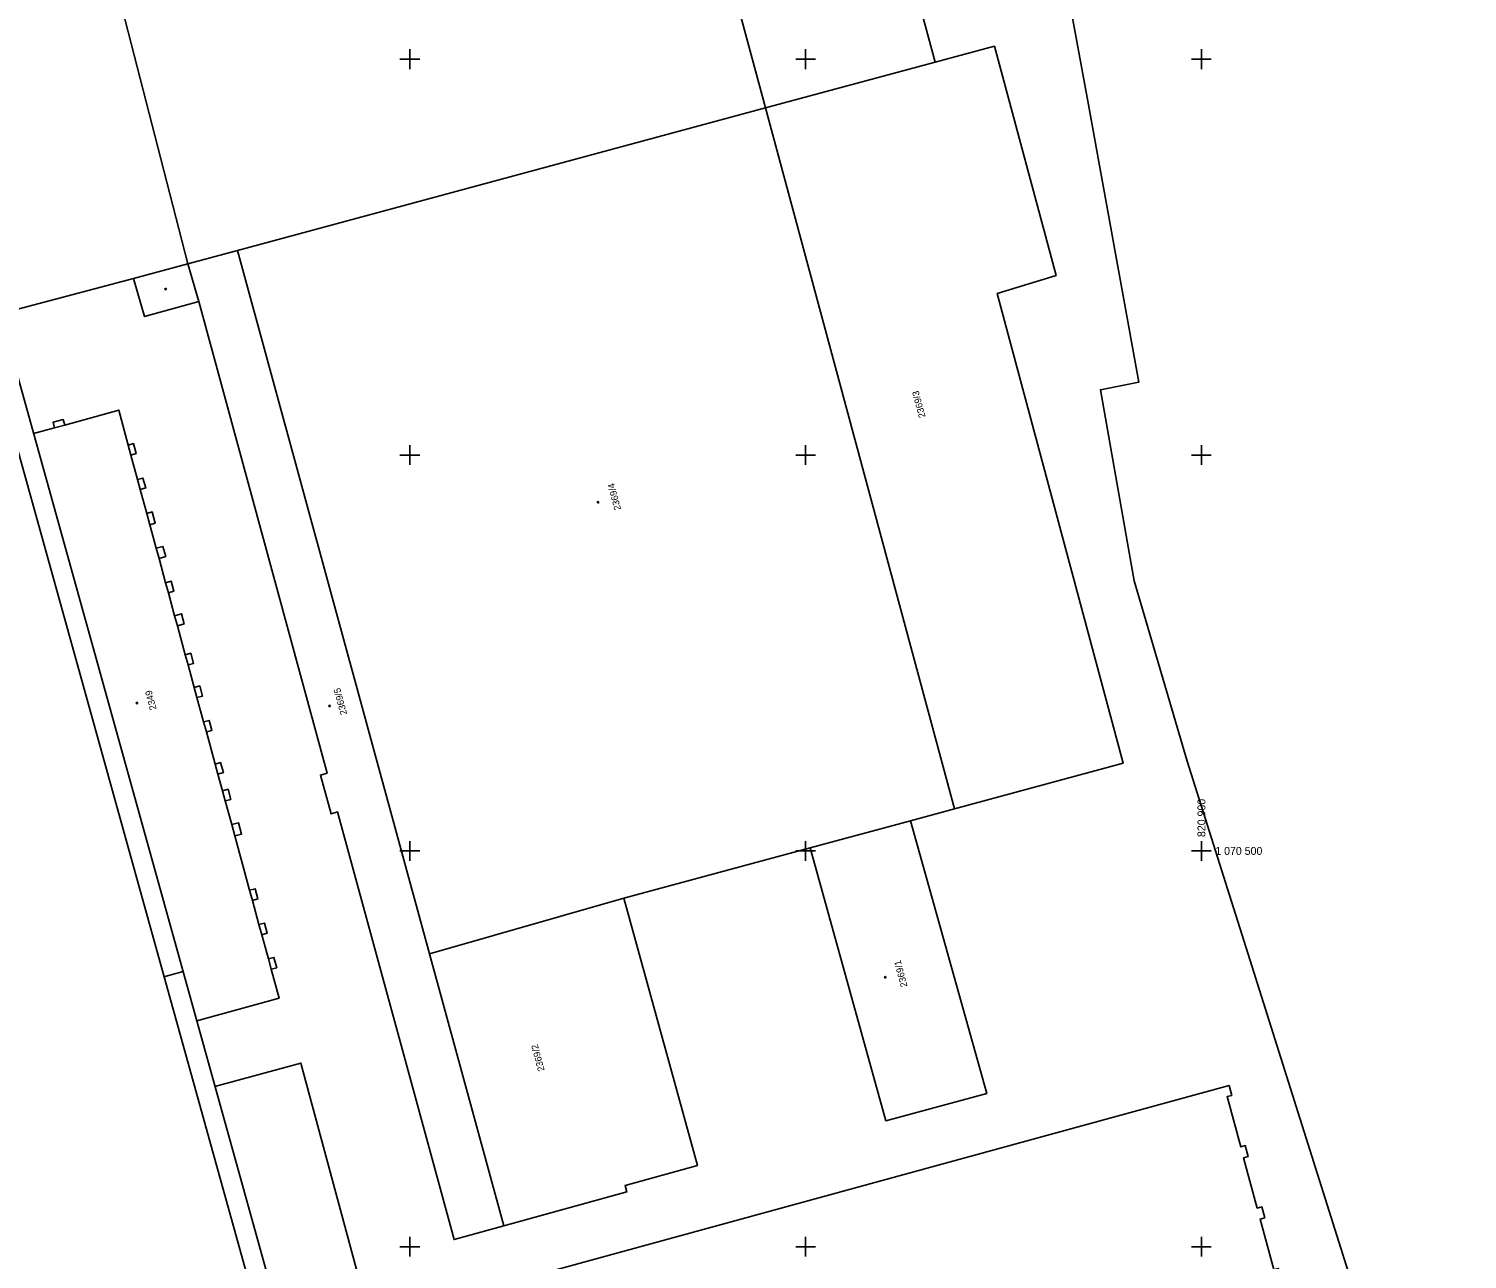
# Model space of a CAD drawing. Extents: x -821172 to -820632, y -1070921 to -1069931.
# Drawn here: x -821048.1 to -820866.4, y -1070551.6 to -1070396.2 of the extents above; entities that cross this region are included whole.
import ezdxf

# ---------------------------------------------------------------- set-up
doc = ezdxf.new("R2010")
doc.units = 0
for name, color, linetype in [('Ram', 7, 'Continuous'), ('Sit', 7, 'Continuous'), ('Vrstva 53', 7, 'Continuous'), ('Vrstva 55', 7, 'Continuous'), ('Vrstva 56', 7, 'Continuous'), ('Vrstva 57', 7, 'Continuous'), ('Vrstva 59', 7, 'Continuous')]:
    doc.layers.add(name, color=color, linetype=linetype)

msp = doc.modelspace()

# ---------------------------------------------------------------- linework, layer by layer
at = {"layer": 'Ram'}
msp.add_line((-821028.65, -1070515.23), (-821031.06, -1070515.9), dxfattribs=at)
for points in [[(-820775.54, -1070880.81), (-820918.62, -1070920.57), (-821143.51, -1070111.23)], [(-820916.88, -1070917.49), (-821140.43, -1070112.97)]]:
    msp.add_lwpolyline(points, dxfattribs=at)
at = {"layer": 'Sit'}
for p, q in [((-821000, -1070398.75), (-821000, -1070400)), ((-820950, -1070398.75), (-820950, -1070400)), ((-820900, -1070398.75), (-820900, -1070400)), ((-821001.25, -1070400), (-821000, -1070400)), ((-820998.75, -1070400), (-821000, -1070400)), ((-821000, -1070401.25), (-821000, -1070400)), ((-820951.25, -1070400), (-820950, -1070400)), ((-820948.75, -1070400), (-820950, -1070400)), ((-820950, -1070401.25), (-820950, -1070400)), ((-820901.25, -1070400), (-820900, -1070400)), ((-820898.75, -1070400), (-820900, -1070400)), ((-820900, -1070401.25), (-820900, -1070400)), ((-821001.25, -1070450), (-821000, -1070450)), ((-821000, -1070448.75), (-821000, -1070450)), ((-820998.75, -1070450), (-821000, -1070450)), ((-821000, -1070451.25), (-821000, -1070450)), ((-820951.25, -1070450), (-820950, -1070450)), ((-820950, -1070448.75), (-820950, -1070450)), ((-820948.75, -1070450), (-820950, -1070450)), ((-820950, -1070451.25), (-820950, -1070450)), ((-820901.25, -1070450), (-820900, -1070450)), ((-820900, -1070448.75), (-820900, -1070450)), ((-820898.75, -1070450), (-820900, -1070450)), ((-820900, -1070451.25), (-820900, -1070450)), ((-821000, -1070498.75), (-821000, -1070500)), ((-820950, -1070498.75), (-820950, -1070500)), ((-820900, -1070498.75), (-820900, -1070500)), ((-821001.25, -1070500), (-821000, -1070500)), ((-820998.75, -1070500), (-821000, -1070500)), ((-821000, -1070501.25), (-821000, -1070500)), ((-820951.25, -1070500), (-820950, -1070500)), ((-820948.75, -1070500), (-820950, -1070500)), ((-820950, -1070501.25), (-820950, -1070500)), ((-820901.25, -1070500), (-820900, -1070500)), ((-820898.75, -1070500), (-820900, -1070500)), ((-820900, -1070501.25), (-820900, -1070500)), ((-821001.25, -1070550), (-821000, -1070550)), ((-821000, -1070548.75), (-821000, -1070550)), ((-820998.75, -1070550), (-821000, -1070550)), ((-821000, -1070551.25), (-821000, -1070550)), ((-820951.25, -1070550), (-820950, -1070550)), ((-820950, -1070548.75), (-820950, -1070550)), ((-820948.75, -1070550), (-820950, -1070550)), ((-820950, -1070551.25), (-820950, -1070550)), ((-820901.25, -1070550), (-820900, -1070550)), ((-820900, -1070548.75), (-820900, -1070550)), ((-820898.75, -1070550), (-820900, -1070550)), ((-820900, -1070551.25), (-820900, -1070550))]:
    msp.add_line(p, q, dxfattribs=at)
at = {"layer": 'Vrstva 53'}
msp.add_lwpolyline([(-820793.34, -1070807.43), (-820797.89, -1070798.01), (-820802.49, -1070786.9), (-820807.86, -1070771.6), (-820839.34, -1070671.73), (-820847.49, -1070649.05), (-820862.12, -1070611.55), (-820870.18, -1070588.9), (-820893.88, -1070513.71), (-820901.78, -1070488.65), (-820908.48, -1070465.88), (-820912.77, -1070441.75), (-820907.91, -1070440.8), (-820914.43, -1070404.83), (-820920.34, -1070372.85), (-820926.76, -1070341.17), (-820933.59, -1070313.73), (-820939.94, -1070294.5), (-820946.33, -1070279.59), (-820953.63, -1070265.09), (-820959.73, -1070254.91)], dxfattribs=at)
at = {"layer": 'Vrstva 55'}
for p, q in [((-820957.29, -1070313.09), (-820933.62, -1070400.37)), ((-820978.59, -1070318.91), (-820955.07, -1070406.16)), ((-821050.57, -1070338.41), (-821028.04, -1070425.85)), ((-820933.62, -1070400.37), (-820955.07, -1070406.16)), ((-820955.07, -1070406.16), (-821021.76, -1070424.16)), ((-820955.07, -1070406.16), (-820931.21, -1070494.68)), ((-821021.76, -1070424.16), (-821028.04, -1070425.85)), ((-821021.76, -1070424.16), (-820997.52, -1070512.98)), ((-821028.04, -1070425.85), (-821026.67, -1070430.62)), ((-820931.21, -1070494.68), (-820936.77, -1070496.18)), ((-820936.77, -1070496.18), (-820949.42, -1070499.6)), ((-820949.42, -1070499.6), (-820972.96, -1070505.96)), ((-820972.96, -1070505.96), (-820997.52, -1070512.98)), ((-820997.52, -1070512.98), (-820988.14, -1070547.37))]:
    msp.add_line(p, q, dxfattribs=at)
for points in [[(-820793.34, -1070807.43), (-820797.89, -1070798.01), (-820802.49, -1070786.9), (-820807.86, -1070771.6), (-820839.34, -1070671.73), (-820847.49, -1070649.05), (-820862.12, -1070611.55), (-820870.18, -1070588.9), (-820893.88, -1070513.71), (-820901.78, -1070488.65), (-820908.48, -1070465.88), (-820912.77, -1070441.75), (-820907.91, -1070440.8), (-820914.43, -1070404.83), (-820920.34, -1070372.85), (-820926.76, -1070341.17), (-820933.59, -1070313.73), (-820939.94, -1070294.5), (-820946.33, -1070279.59), (-820953.63, -1070265.09), (-820959.73, -1070254.91)], [(-820933.62, -1070400.37), (-820926.16, -1070398.36), (-820918.36, -1070427.34), (-820925.8, -1070429.59), (-820909.9, -1070488.92), (-820931.21, -1070494.68)], [(-821026.67, -1070430.62), (-821033.52, -1070432.51), (-821034.91, -1070427.71), (-821051.74, -1070432.15)], [(-820988.14, -1070547.37), (-820994.41, -1070549.1), (-821009.12, -1070495.08), (-821009.96, -1070495.32), (-821011.3, -1070490.42), (-821010.46, -1070490.16), (-821026.67, -1070430.62)], [(-821047.54, -1070447.28), (-821044.88, -1070446.56), (-821045.07, -1070445.86), (-821043.79, -1070445.51), (-821043.6, -1070446.21), (-821036.77, -1070444.31), (-821035.6, -1070448.74), (-821034.91, -1070448.55), (-821034.56, -1070449.82), (-821035.26, -1070450.01), (-821034.41, -1070453.09), (-821033.72, -1070452.9), (-821033.37, -1070454.16), (-821034.07, -1070454.35), (-821033.24, -1070457.37), (-821032.55, -1070457.18), (-821032.16, -1070458.61), (-821032.85, -1070458.8), (-821032.04, -1070461.78), (-821031.19, -1070461.55), (-821030.84, -1070462.83), (-821031.69, -1070463.06), (-821030.85, -1070466.13), (-821030.15, -1070465.94), (-821029.81, -1070467.21), (-821030.5, -1070467.4), (-821029.72, -1070470.29), (-821028.86, -1070470.05), (-821028.52, -1070471.33), (-821029.37, -1070471.56), (-821028.37, -1070475.22), (-821027.67, -1070475.03), (-821027.32, -1070476.31), (-821028.02, -1070476.5), (-821027.23, -1070479.36), (-821026.54, -1070479.17), (-821026.19, -1070480.45), (-821026.89, -1070480.64), (-821026.05, -1070483.71), (-821025.35, -1070483.52), (-821025, -1070484.79), (-821025.7, -1070484.98), (-821024.59, -1070489.03), (-821023.9, -1070488.84), (-821023.55, -1070490.11), (-821024.24, -1070490.3), (-821023.67, -1070492.41), (-821022.97, -1070492.22), (-821022.63, -1070493.49), (-821023.32, -1070493.68), (-821022.5, -1070496.68), (-821021.65, -1070496.45), (-821021.26, -1070497.87), (-821022.11, -1070498.1), (-821020.24, -1070504.97), (-821019.54, -1070504.78), (-821019.19, -1070506.06), (-821019.89, -1070506.25), (-821019.06, -1070509.3), (-821018.36, -1070509.11), (-821018.01, -1070510.4), (-821018.7, -1070510.59), (-821017.87, -1070513.64), (-821017.17, -1070513.45), (-821016.82, -1070514.75), (-821017.51, -1070514.93), (-821016.51, -1070518.6), (-821026.93, -1070521.45)], [(-820936.77, -1070496.18), (-820927.12, -1070530.65), (-820939.86, -1070534.08), (-820949.42, -1070499.6)], [(-820972.96, -1070505.96), (-820963.68, -1070539.75), (-820972.81, -1070542.27), (-820972.59, -1070543.08), (-820988.14, -1070547.37)], [(-821024.62, -1070529.75), (-821013.78, -1070526.79), (-820993.35, -1070602.46), (-821003.64, -1070605.27)], [(-820987.3, -1070553.53), (-820984.32, -1070553.15), (-820984.15, -1070553.64), (-820896.5, -1070529.65), (-820896.17, -1070530.88), (-820896.75, -1070531.03), (-820895.04, -1070537.38), (-820894.46, -1070537.22), (-820894.09, -1070538.61), (-820894.67, -1070538.77), (-820892.95, -1070545.12), (-820892.38, -1070544.96), (-820892, -1070546.35), (-820892.58, -1070546.51), (-820890.86, -1070552.89), (-820890.28, -1070552.73), (-820889.96, -1070553.93), (-820980.44, -1070578.68)]]:
    msp.add_lwpolyline(points, dxfattribs=at)
at = {"layer": 'Vrstva 56'}
for p, q in [((-821034.91, -1070427.71), (-821028.04, -1070425.85)), ((-821044.88, -1070446.56), (-821043.6, -1070446.21)), ((-821035.6, -1070448.74), (-821035.26, -1070450.01)), ((-821034.41, -1070453.09), (-821034.07, -1070454.35)), ((-821033.24, -1070457.37), (-821032.85, -1070458.8)), ((-821032.04, -1070461.78), (-821031.69, -1070463.06)), ((-821030.85, -1070466.13), (-821030.5, -1070467.4)), ((-821029.72, -1070470.29), (-821029.37, -1070471.56)), ((-821028.37, -1070475.22), (-821028.02, -1070476.5)), ((-821027.23, -1070479.36), (-821026.89, -1070480.64)), ((-821026.05, -1070483.71), (-821025.7, -1070484.98)), ((-821024.59, -1070489.03), (-821024.24, -1070490.3)), ((-821023.67, -1070492.41), (-821023.32, -1070493.68)), ((-821022.5, -1070496.68), (-821022.11, -1070498.1)), ((-821020.24, -1070504.97), (-821019.89, -1070506.25)), ((-821019.06, -1070509.3), (-821018.7, -1070510.59)), ((-821017.87, -1070513.64), (-821017.51, -1070514.93))]:
    msp.add_line(p, q, dxfattribs=at)
at = {"layer": 'Vrstva 59'}
for centre in [(-821030.85, -1070429.03), (-820976.22, -1070455.96), (-821034.48, -1070481.32), (-821010.14, -1070481.69), (-820939.94, -1070515.95)]:
    msp.add_circle(centre, 0.0875, dxfattribs=at)

# ---------------------------------------------------------------- texts
at = {"layer": 'Sit'}
msp.add_text('820 900', height=1, rotation=90, dxfattribs=at).set_placement((-820899.5, -1070498.25))
msp.add_text('1 070 500', height=1, dxfattribs=at).set_placement((-820898.25, -1070500.5))
at = {"layer": 'Vrstva 57'}
for s, p in [('2369/3', (-820934.84, -1070445.17)), ('2369/4', (-820973.31, -1070456.85)), ('2349', (-821031.99, -1070482.08)), ('2369/5', (-821007.92, -1070482.7)), ('2369/1', (-820937.12, -1070517.09)), ('2369/2', (-820982.96, -1070527.72))]:
    msp.add_text(s, height=0.85, rotation=105, dxfattribs=at).set_placement(p)

doc.saveas('drawing.dxf')
